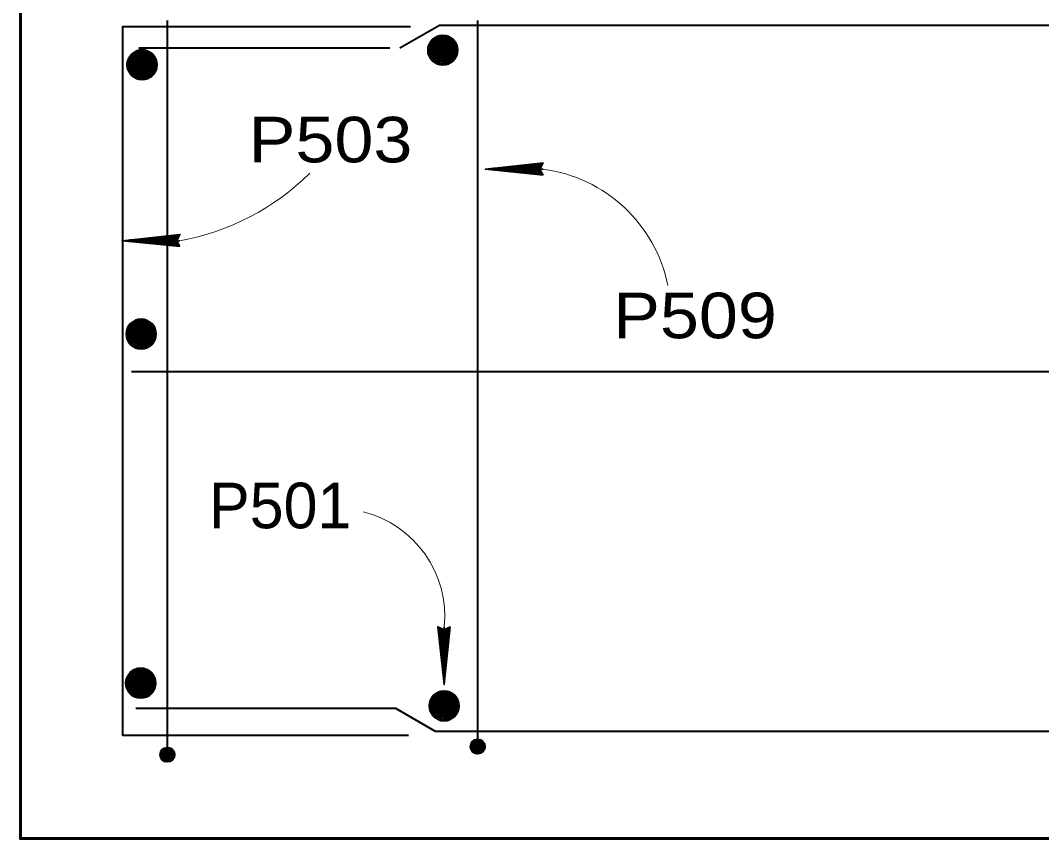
# Model space of a CAD drawing. Extents: x 6.34 to 9.53, y -1.46 to 0.53.
# Drawn here: x 6.7189 to 6.9057, y 0.0454 to 0.195 of the extents above; entities that cross this region are included whole.
import ezdxf

# ---------------------------------------------------------------- set-up
doc = ezdxf.new("R2010")
doc.units = 0
doc.header["$LTSCALE"] = 0.0033
doc.layers.add('1', color=7, linetype='Continuous', lineweight=40)

msp = doc.modelspace()

# ---------------------------------------------------------------- linework, layer by layer
at = {"layer": '1'}
for p, q in [((6.74575, 0.195), (6.74575, 0.062167)), ((6.8025, 0.195), (6.8025, 0.063667)), ((6.794083, 0.191167), (6.798667, 0.189)), ((6.794333, 0.19075), (6.79825, 0.19)), ((6.794333, 0.190583), (6.79825, 0.189833)), ((6.794417, 0.191167), (6.798333, 0.1905)), ((6.794417, 0.191), (6.798333, 0.19025)), ((6.7945, 0.1915), (6.798333, 0.190833)), ((6.796417, 0.190667), (6.79775, 0.191667)), ((6.7985, 0.190833), (6.79725, 0.192)), ((6.7395, 0.188833), (6.743333, 0.188167)), ((6.740583, 0.19), (6.7865, 0.19)), ((6.741417, 0.188), (6.74275, 0.189)), ((6.7435, 0.188167), (6.74225, 0.189333)), ((6.794, 0.188917), (6.797917, 0.188167)), ((6.794, 0.18875), (6.797833, 0.188)), ((6.794083, 0.189333), (6.798, 0.188583)), ((6.794167, 0.18975), (6.798, 0.189)), ((6.794167, 0.189583), (6.798, 0.188833)), ((6.79425, 0.190167), (6.798083, 0.1895)), ((6.79425, 0.19), (6.798083, 0.18925)), ((6.794333, 0.190333), (6.798167, 0.189583)), ((6.739083, 0.1885), (6.743667, 0.186333)), ((6.739167, 0.187083), (6.743, 0.186333)), ((6.739167, 0.186917), (6.743, 0.186167)), ((6.73925, 0.1875), (6.743083, 0.186833)), ((6.73925, 0.187333), (6.743083, 0.186583)), ((6.739333, 0.188083), (6.74325, 0.187333)), ((6.739333, 0.187917), (6.74325, 0.187167)), ((6.739333, 0.187667), (6.743167, 0.186917)), ((6.739417, 0.1885), (6.743333, 0.187833)), ((6.739417, 0.188333), (6.743333, 0.187583)), ((6.793917, 0.188417), (6.79775, 0.187667)), ((6.793917, 0.18825), (6.79775, 0.1875)), ((6.794, 0.1885), (6.797833, 0.187833)), ((6.79825, 0.188), (6.7945, 0.187583)), ((6.738917, 0.18575), (6.74275, 0.185)), ((6.738917, 0.185583), (6.74275, 0.184833)), ((6.739, 0.18625), (6.742917, 0.1855)), ((6.739, 0.186083), (6.742833, 0.185333)), ((6.739, 0.185833), (6.742833, 0.185167)), ((6.739083, 0.186667), (6.743, 0.185917)), ((6.74325, 0.185333), (6.7395, 0.184917)), ((6.743333, 0.138917), (6.742083, 0.140083)), ((6.738917, 0.13925), (6.7435, 0.137083)), ((6.739083, 0.13825), (6.742917, 0.137583)), ((6.739167, 0.138833), (6.743083, 0.138083)), ((6.739167, 0.138667), (6.743083, 0.137917)), ((6.739167, 0.138417), (6.743, 0.137667)), ((6.73925, 0.13925), (6.743167, 0.138583)), ((6.73925, 0.139083), (6.743167, 0.138333)), ((6.739333, 0.139583), (6.743167, 0.138917)), ((6.74125, 0.13875), (6.742583, 0.13975)), ((6.73875, 0.1365), (6.742583, 0.13575)), ((6.738833, 0.137), (6.74275, 0.13625)), ((6.738833, 0.136833), (6.742667, 0.136083)), ((6.738833, 0.136583), (6.742667, 0.135917)), ((6.738917, 0.137417), (6.742833, 0.136667)), ((6.739, 0.137833), (6.742833, 0.137083)), ((6.739, 0.137667), (6.742833, 0.136917)), ((6.739083, 0.138083), (6.742917, 0.137333)), ((6.73875, 0.136333), (6.742583, 0.135583)), ((6.743083, 0.136083), (6.739333, 0.135667)), ((6.738833, 0.075417), (6.743417, 0.07325)), ((6.739083, 0.075), (6.743, 0.07425)), ((6.739083, 0.074833), (6.743, 0.074083)), ((6.739167, 0.075417), (6.743083, 0.07475)), ((6.739167, 0.07525), (6.743083, 0.0745)), ((6.73925, 0.07575), (6.743083, 0.075083)), ((6.741167, 0.074917), (6.7425, 0.075917)), ((6.74325, 0.075083), (6.742, 0.07625)), ((6.73875, 0.073167), (6.742667, 0.072417)), ((6.73875, 0.073), (6.742583, 0.07225)), ((6.738833, 0.073583), (6.74275, 0.072833)), ((6.738917, 0.074), (6.74275, 0.07325)), ((6.738917, 0.073833), (6.74275, 0.073083)), ((6.739, 0.074417), (6.742833, 0.07375)), ((6.739, 0.07425), (6.742833, 0.0735)), ((6.739083, 0.074583), (6.742917, 0.073833)), ((6.738667, 0.072667), (6.7425, 0.071917)), ((6.738667, 0.0725), (6.7425, 0.07175)), ((6.73875, 0.07275), (6.742583, 0.072083)), ((6.743, 0.07225), (6.73925, 0.071833)), ((6.794333, 0.07125), (6.798917, 0.069083)), ((6.794667, 0.07125), (6.798583, 0.070583)), ((6.794667, 0.071083), (6.798583, 0.070333)), ((6.79475, 0.071583), (6.798583, 0.070917)), ((6.796667, 0.07075), (6.798, 0.07175)), ((6.79875, 0.070917), (6.7975, 0.072083)), ((6.794333, 0.069417), (6.79825, 0.068667)), ((6.794417, 0.069833), (6.79825, 0.069083)), ((6.794417, 0.069667), (6.79825, 0.068917)), ((6.7945, 0.07025), (6.798333, 0.069583)), ((6.7945, 0.070083), (6.798333, 0.069333)), ((6.794583, 0.070833), (6.7985, 0.070083)), ((6.794583, 0.070667), (6.7985, 0.069917)), ((6.794583, 0.070417), (6.798417, 0.069667)), ((6.794167, 0.0685), (6.798, 0.06775)), ((6.794167, 0.068333), (6.798, 0.067583)), ((6.79425, 0.069), (6.798167, 0.06825)), ((6.79425, 0.068833), (6.798083, 0.068083)), ((6.79425, 0.068583), (6.798083, 0.067917)), ((6.7985, 0.068083), (6.79475, 0.067667)), ((6.745167, 0.061917), (6.744833, 0.059917)), ((6.74525, 0.061833), (6.744917, 0.059917)), ((6.745333, 0.061833), (6.745, 0.059917)), ((6.745417, 0.061833), (6.745083, 0.059833)), ((6.746583, 0.061667), (6.745083, 0.06175)), ((6.746583, 0.061583), (6.745083, 0.061667)), ((6.745667, 0.061833), (6.74525, 0.059833)), ((6.745833, 0.06175), (6.745417, 0.059833)), ((6.745917, 0.06175), (6.7455, 0.059833)), ((6.746, 0.06175), (6.745583, 0.05975)), ((6.746083, 0.06175), (6.74575, 0.05975)), ((6.746167, 0.061667), (6.745833, 0.05975)), ((6.746333, 0.061667), (6.745917, 0.059667)), ((6.746417, 0.061667), (6.746, 0.059667)), ((6.7465, 0.061667), (6.746167, 0.059667)), ((6.746583, 0.061667), (6.74625, 0.059667)), ((6.801917, 0.063417), (6.801583, 0.061417)), ((6.802, 0.063333), (6.801667, 0.061417)), ((6.802083, 0.063333), (6.80175, 0.061417)), ((6.80325, 0.062), (6.80175, 0.062167)), ((6.80325, 0.061833), (6.80175, 0.062)), ((6.80325, 0.06175), (6.80175, 0.061833)), ((6.80325, 0.06175), (6.80175, 0.061833)), ((6.80325, 0.061667), (6.80175, 0.06175)), ((6.80325, 0.061583), (6.80175, 0.061667)), ((6.802167, 0.063333), (6.801833, 0.061333)), ((6.803333, 0.063167), (6.801833, 0.06325)), ((6.803333, 0.063083), (6.801833, 0.063167)), ((6.803333, 0.063), (6.801833, 0.063083)), ((6.803333, 0.062917), (6.801833, 0.063)), ((6.803333, 0.062833), (6.801833, 0.062917)), ((6.803333, 0.062667), (6.801833, 0.06275)), ((6.803333, 0.062583), (6.801833, 0.062667)), ((6.803333, 0.0625), (6.801833, 0.062583)), ((6.803333, 0.062417), (6.801833, 0.0625)), ((6.803333, 0.062333), (6.801833, 0.062417)), ((6.803333, 0.06225), (6.801833, 0.062333)), ((6.803333, 0.062167), (6.801833, 0.06225)), ((6.802417, 0.063333), (6.802, 0.061333)), ((6.802583, 0.06325), (6.802167, 0.061333)), ((6.802667, 0.06325), (6.80225, 0.061333)), ((6.80275, 0.06325), (6.802333, 0.06125)), ((6.802833, 0.06325), (6.8025, 0.06125)), ((6.802917, 0.063167), (6.802583, 0.06125)), ((6.803083, 0.063167), (6.802667, 0.061167)), ((6.803167, 0.063167), (6.80275, 0.061167)), ((6.80325, 0.063167), (6.802917, 0.061167)), ((6.803333, 0.063167), (6.803, 0.061167)), ((6.8035, 0.063083), (6.803167, 0.061167)), ((6.7465, 0.0605), (6.745, 0.060667)), ((6.7465, 0.060333), (6.745, 0.0605)), ((6.7465, 0.06025), (6.745, 0.060333)), ((6.7465, 0.06025), (6.745, 0.060333)), ((6.7465, 0.060167), (6.745, 0.06025)), ((6.7465, 0.060083), (6.745, 0.060167)), ((6.7465, 0.06), (6.745, 0.060083)), ((6.7465, 0.059917), (6.745, 0.06)), ((6.7465, 0.059833), (6.745, 0.059917)), ((6.7465, 0.05975), (6.745, 0.059833)), ((6.746583, 0.0615), (6.745083, 0.061583)), ((6.746583, 0.061417), (6.745083, 0.0615)), ((6.746583, 0.061333), (6.745083, 0.061417)), ((6.746583, 0.061167), (6.745083, 0.06125)), ((6.746583, 0.061083), (6.745083, 0.061167)), ((6.746583, 0.061), (6.745083, 0.061083)), ((6.746583, 0.060917), (6.745083, 0.061)), ((6.746583, 0.060833), (6.745083, 0.060917)), ((6.746583, 0.06075), (6.745083, 0.060833)), ((6.746583, 0.060667), (6.745083, 0.06075)), ((6.74675, 0.061583), (6.746417, 0.059667)), ((6.80325, 0.0615), (6.80175, 0.061583)), ((6.80325, 0.061417), (6.80175, 0.0615)), ((6.80325, 0.061333), (6.80175, 0.061417)), ((6.80325, 0.06125), (6.80175, 0.061333)), ((6.80325, 0.061083), (6.80175, 0.061167)), ((6.7465, 0.059583), (6.745, 0.059667))]:
    msp.add_line(p, q, dxfattribs=at)
at = {"layer": '1', "lineweight": 60}
for p, q in [((6.794333, 0.191167), (6.794167, 0.18825)), ((6.794583, 0.191167), (6.794333, 0.18825)), ((6.79475, 0.191167), (6.794583, 0.188167)), ((6.794917, 0.191167), (6.794667, 0.188167)), ((6.795083, 0.191167), (6.794917, 0.188167)), ((6.795333, 0.191167), (6.795167, 0.188167)), ((6.795583, 0.191167), (6.795333, 0.188167)), ((6.795667, 0.191083), (6.7955, 0.188167)), ((6.795833, 0.191083), (6.795667, 0.188167)), ((6.796, 0.191083), (6.795833, 0.188167)), ((6.79625, 0.191083), (6.796, 0.188167)), ((6.796417, 0.191083), (6.79625, 0.188167)), ((6.796667, 0.191), (6.796417, 0.188083)), ((6.796917, 0.191), (6.796667, 0.188083)), ((6.797083, 0.191), (6.796917, 0.188083)), ((6.797167, 0.191), (6.797, 0.188083)), ((6.797333, 0.191), (6.797167, 0.188083)), ((6.797417, 0.191), (6.79725, 0.188083)), ((6.797667, 0.190917), (6.797417, 0.188)), ((6.797833, 0.190917), (6.797667, 0.188)), ((6.798, 0.190917), (6.79775, 0.188)), ((6.798167, 0.190917), (6.798, 0.188)), ((6.798417, 0.190917), (6.79825, 0.188)), ((6.798667, 0.189), (6.7985, 0.190833)), ((6.798667, 0.189), (6.793917, 0.18825)), ((6.739333, 0.1885), (6.739167, 0.185583)), ((6.739583, 0.1885), (6.739333, 0.185583)), ((6.73975, 0.1885), (6.739583, 0.1855)), ((6.739917, 0.1885), (6.739667, 0.1855)), ((6.740083, 0.1885), (6.739917, 0.1855)), ((6.740333, 0.1885), (6.740167, 0.1855)), ((6.740583, 0.1885), (6.740333, 0.1855)), ((6.740667, 0.188417), (6.7405, 0.1855)), ((6.740833, 0.188417), (6.740667, 0.1855)), ((6.741, 0.188417), (6.740833, 0.1855)), ((6.74125, 0.188417), (6.741, 0.1855)), ((6.741417, 0.188417), (6.74125, 0.1855)), ((6.741667, 0.188333), (6.741417, 0.185417)), ((6.741917, 0.188333), (6.741667, 0.185417)), ((6.742083, 0.188333), (6.741917, 0.185417)), ((6.742167, 0.188333), (6.742, 0.185417)), ((6.742333, 0.188333), (6.742167, 0.185417)), ((6.742417, 0.188333), (6.74225, 0.185417)), ((6.742667, 0.18825), (6.742417, 0.185333)), ((6.742833, 0.18825), (6.742667, 0.185333)), ((6.743, 0.18825), (6.74275, 0.185333)), ((6.743167, 0.18825), (6.743, 0.185333)), ((6.743417, 0.18825), (6.74325, 0.185333)), ((6.743667, 0.186333), (6.7435, 0.188167)), ((6.743667, 0.186333), (6.738917, 0.185583)), ((6.739167, 0.13925), (6.739, 0.136333)), ((6.739417, 0.13925), (6.739167, 0.136333)), ((6.739583, 0.13925), (6.739417, 0.13625)), ((6.73975, 0.13925), (6.7395, 0.13625)), ((6.739917, 0.13925), (6.73975, 0.13625)), ((6.740167, 0.13925), (6.74, 0.13625)), ((6.740417, 0.13925), (6.740167, 0.13625)), ((6.7405, 0.139167), (6.740333, 0.13625)), ((6.740667, 0.139167), (6.7405, 0.13625)), ((6.740833, 0.139167), (6.740667, 0.13625)), ((6.741083, 0.139167), (6.740833, 0.13625)), ((6.74125, 0.139167), (6.741083, 0.13625)), ((6.7415, 0.139083), (6.74125, 0.136167)), ((6.74175, 0.139083), (6.7415, 0.136167)), ((6.741917, 0.139083), (6.74175, 0.136167)), ((6.742, 0.139083), (6.741833, 0.136167)), ((6.742167, 0.139083), (6.742, 0.136167)), ((6.74225, 0.139083), (6.742083, 0.136167)), ((6.7425, 0.139), (6.74225, 0.136083)), ((6.742667, 0.139), (6.7425, 0.136083)), ((6.742833, 0.139), (6.742583, 0.136083)), ((6.743, 0.139), (6.742833, 0.136083)), ((6.74325, 0.139), (6.743083, 0.136083)), ((6.7435, 0.137083), (6.743333, 0.138917)), ((6.7435, 0.137083), (6.73875, 0.136333)), ((6.739083, 0.075417), (6.738917, 0.0725)), ((6.739333, 0.075417), (6.739083, 0.0725)), ((6.7395, 0.075417), (6.739333, 0.072417)), ((6.739667, 0.075417), (6.739417, 0.072417)), ((6.739833, 0.075417), (6.739667, 0.072417)), ((6.740083, 0.075417), (6.739917, 0.072417)), ((6.740333, 0.075417), (6.740083, 0.072417)), ((6.740417, 0.075333), (6.74025, 0.072417)), ((6.740583, 0.075333), (6.740417, 0.072417)), ((6.74075, 0.075333), (6.740583, 0.072417)), ((6.741, 0.075333), (6.74075, 0.072417)), ((6.741167, 0.075333), (6.741, 0.072417)), ((6.741417, 0.07525), (6.741167, 0.072333)), ((6.741667, 0.07525), (6.741417, 0.072333)), ((6.741833, 0.07525), (6.741667, 0.072333)), ((6.741917, 0.07525), (6.74175, 0.072333)), ((6.742083, 0.07525), (6.741917, 0.072333)), ((6.742167, 0.07525), (6.742, 0.072333)), ((6.742417, 0.075167), (6.742167, 0.07225)), ((6.742583, 0.075167), (6.742417, 0.07225)), ((6.74275, 0.075167), (6.7425, 0.07225)), ((6.742917, 0.075167), (6.74275, 0.07225)), ((6.743167, 0.075167), (6.743, 0.07225)), ((6.743417, 0.07325), (6.74325, 0.075083)), ((6.743417, 0.07325), (6.738667, 0.0725)), ((6.794583, 0.07125), (6.794417, 0.068333)), ((6.794833, 0.07125), (6.794583, 0.068333)), ((6.795, 0.07125), (6.794833, 0.06825)), ((6.795167, 0.07125), (6.794917, 0.06825)), ((6.795333, 0.07125), (6.795167, 0.06825)), ((6.795583, 0.07125), (6.795417, 0.06825)), ((6.795833, 0.07125), (6.795583, 0.06825)), ((6.795917, 0.071167), (6.79575, 0.06825)), ((6.796083, 0.071167), (6.795917, 0.06825)), ((6.79625, 0.071167), (6.796083, 0.06825)), ((6.7965, 0.071167), (6.79625, 0.06825)), ((6.796667, 0.071167), (6.7965, 0.06825)), ((6.796917, 0.071083), (6.796667, 0.068167)), ((6.797167, 0.071083), (6.796917, 0.068167)), ((6.797333, 0.071083), (6.797167, 0.068167)), ((6.797417, 0.071083), (6.79725, 0.068167)), ((6.797583, 0.071083), (6.797417, 0.068167)), ((6.797667, 0.071083), (6.7975, 0.068167)), ((6.797917, 0.071), (6.797667, 0.068083)), ((6.798083, 0.071), (6.797917, 0.068083)), ((6.79825, 0.071), (6.798, 0.068083)), ((6.798417, 0.071), (6.79825, 0.068083)), ((6.798667, 0.071), (6.7985, 0.068083)), ((6.798917, 0.069083), (6.79875, 0.070917)), ((6.798917, 0.069083), (6.794167, 0.068333))]:
    msp.add_line(p, q, dxfattribs=at)
at = {"layer": '1', "lineweight": 35}
for p, q in [((6.81425, 0.168917), (6.806917, 0.168083)), ((6.81425, 0.16875), (6.806917, 0.168)), ((6.81425, 0.168667), (6.806917, 0.167833)), ((6.814333, 0.1685), (6.807, 0.16775)), ((6.8145, 0.167833), (6.803917, 0.167833)), ((6.81425, 0.167), (6.806417, 0.168)), ((6.81425, 0.167), (6.806417, 0.167833)), ((6.81425, 0.166833), (6.806417, 0.16775)), ((6.81425, 0.166833), (6.806417, 0.16775)), ((6.81425, 0.166917), (6.806417, 0.16775)), ((6.747833, 0.155833), (6.7405, 0.155)), ((6.747833, 0.155667), (6.7405, 0.154917)), ((6.747833, 0.155583), (6.7405, 0.15475)), ((6.747917, 0.155417), (6.740583, 0.154667)), ((6.748083, 0.15475), (6.7375, 0.15475)), ((6.747833, 0.153917), (6.74, 0.154917)), ((6.747833, 0.153917), (6.74, 0.15475)), ((6.747833, 0.15375), (6.74, 0.154667)), ((6.747833, 0.15375), (6.74, 0.154667)), ((6.747833, 0.153833), (6.74, 0.154667)), ((6.796417, 0.084167), (6.796417, 0.073583)), ((6.795333, 0.083917), (6.796167, 0.076583)), ((6.7955, 0.083917), (6.79625, 0.076583)), ((6.795583, 0.083917), (6.796417, 0.076583)), ((6.79575, 0.084), (6.7965, 0.076667)), ((6.79725, 0.083917), (6.79625, 0.076083)), ((6.79725, 0.083917), (6.796417, 0.076083)), ((6.797417, 0.083917), (6.7965, 0.076083)), ((6.797417, 0.083917), (6.7965, 0.076083)), ((6.797333, 0.083917), (6.7965, 0.076083))]:
    msp.add_line(p, q, dxfattribs=at)
at = {"layer": '1', "lineweight": 60}
for points in [[(7.30225, 0.212083), (7.30225, 0.045417), (6.718917, 0.045417), (6.718917, 0.212083)], [(6.7935, 0.1895), (6.798667, 0.190167), (6.794083, 0.191167)], [(6.79775, 0.1875), (6.79775, 0.191667), (6.796083, 0.187), (6.796583, 0.192167), (6.7945, 0.187583), (6.79525, 0.192083), (6.796833, 0.187083), (6.793667, 0.190417), (6.7985, 0.190833), (6.79525, 0.187167), (6.79725, 0.192), (6.794083, 0.191167), (6.793917, 0.18825)], [(6.7945, 0.187583), (6.796, 0.189833), (6.793833, 0.19075), (6.795833, 0.192167), (6.796, 0.189917), (6.797667, 0.187583), (6.793667, 0.189917), (6.796417, 0.190667)], [(6.79725, 0.192), (6.796, 0.189833), (6.79825, 0.188)], [(6.74275, 0.184833), (6.74275, 0.189), (6.741083, 0.184333), (6.741583, 0.1895), (6.7395, 0.184917), (6.74025, 0.189417), (6.741833, 0.184417), (6.738667, 0.18775), (6.7435, 0.188167), (6.74025, 0.1845), (6.74225, 0.189333), (6.739083, 0.1885), (6.738917, 0.185583)], [(6.7395, 0.184917), (6.741, 0.187167), (6.738833, 0.188083), (6.740833, 0.1895), (6.741, 0.18725), (6.742667, 0.184917), (6.738667, 0.18725), (6.741417, 0.188)], [(6.74225, 0.189333), (6.741, 0.187167), (6.74325, 0.185333)], [(6.7385, 0.186833), (6.743667, 0.1875), (6.739083, 0.1885)], [(6.742583, 0.135583), (6.742583, 0.13975), (6.740917, 0.135083), (6.741417, 0.14025), (6.739333, 0.135667), (6.740083, 0.140167), (6.741667, 0.135167), (6.7385, 0.1385), (6.743333, 0.138917), (6.740083, 0.13525), (6.742083, 0.140083), (6.738917, 0.13925), (6.73875, 0.136333)], [(6.739333, 0.135667), (6.740833, 0.137917), (6.738667, 0.138833), (6.740667, 0.14025), (6.740833, 0.138), (6.7425, 0.135667), (6.7385, 0.138), (6.74125, 0.13875)], [(6.742083, 0.140083), (6.740833, 0.137917), (6.743083, 0.136083)], [(6.738333, 0.137583), (6.7435, 0.13825), (6.738917, 0.13925)], [(6.73825, 0.07375), (6.743417, 0.074417), (6.738833, 0.075417)], [(6.7425, 0.07175), (6.7425, 0.075917), (6.740833, 0.07125), (6.741333, 0.076417), (6.73925, 0.071833), (6.74, 0.076333), (6.741583, 0.071333), (6.738417, 0.074667), (6.74325, 0.075083), (6.74, 0.071417), (6.742, 0.07625), (6.738833, 0.075417), (6.738667, 0.0725)], [(6.73925, 0.071833), (6.74075, 0.074083), (6.738583, 0.075), (6.740583, 0.076417), (6.74075, 0.074167), (6.742417, 0.071833), (6.738417, 0.074167), (6.741167, 0.074917)], [(6.742, 0.07625), (6.74075, 0.074083), (6.743, 0.07225)], [(6.79375, 0.069583), (6.798917, 0.07025), (6.794333, 0.07125)], [(6.798, 0.067583), (6.798, 0.07175), (6.796333, 0.067083), (6.796833, 0.07225), (6.79475, 0.067667), (6.7955, 0.072167), (6.797083, 0.067167), (6.793917, 0.0705), (6.79875, 0.070917), (6.7955, 0.06725), (6.7975, 0.072083), (6.794333, 0.07125), (6.794167, 0.068333)], [(6.79475, 0.067667), (6.79625, 0.069917), (6.794083, 0.070833), (6.796083, 0.07225), (6.79625, 0.07), (6.797917, 0.067667), (6.793917, 0.07), (6.796667, 0.07075)], [(6.7975, 0.072083), (6.79625, 0.069917), (6.7985, 0.068083)]]:
    msp.add_lwpolyline(points, dxfattribs=at)
at = {"layer": '1'}
for points in [[(6.789917, 0.06425), (6.737667, 0.06425), (6.737667, 0.193917), (6.79025, 0.193917)], [(6.788333, 0.19), (6.795583, 0.194167), (7.16075, 0.194167)], [(6.793917, 0.18825), (6.796, 0.187), (6.79775, 0.1875), (6.798667, 0.189)], [(6.738917, 0.185583), (6.741, 0.184333), (6.74275, 0.184833), (6.743667, 0.186333)], [(6.73875, 0.136333), (6.740833, 0.135083), (6.742583, 0.135583), (6.7435, 0.137083)], [(6.73925, 0.130833), (7.159583, 0.130833), (7.280917, 0.130833)], [(6.738667, 0.0725), (6.74075, 0.07125), (6.7425, 0.07175), (6.743417, 0.07325)], [(6.74, 0.06925), (6.7875, 0.06925), (6.79475, 0.065083), (7.168917, 0.065083)], [(6.794167, 0.068333), (6.79625, 0.067083), (6.798, 0.067583), (6.798917, 0.069083)], [(6.8025, 0.063583), (6.802833, 0.061), (6.803333, 0.063333), (6.80225, 0.061), (6.801833, 0.063417), (6.8015, 0.061417), (6.803583, 0.061417), (6.80125, 0.062333), (6.803833, 0.062083), (6.8015, 0.063083), (6.803833, 0.06275), (6.80125, 0.061917), (6.803, 0.0635), (6.803167, 0.061083), (6.801333, 0.06275), (6.80375, 0.061667), (6.803333, 0.063333), (6.801833, 0.063417), (6.80125, 0.062333), (6.8015, 0.061417), (6.80225, 0.061), (6.803167, 0.061083), (6.80375, 0.061667), (6.802667, 0.062333), (6.80175, 0.061167), (6.8015, 0.063083), (6.802667, 0.062333), (6.803167, 0.063417), (6.803833, 0.062417), (6.80275, 0.062333), (6.8015, 0.0615), (6.80275, 0.0635), (6.803083, 0.062167), (6.803583, 0.061417)], [(6.74575, 0.062083), (6.746083, 0.0595), (6.746583, 0.061833), (6.7455, 0.0595), (6.745083, 0.061917), (6.74475, 0.059917), (6.746833, 0.059917), (6.7445, 0.060833), (6.747083, 0.060583), (6.74475, 0.061583), (6.747083, 0.06125), (6.7445, 0.060417), (6.74625, 0.062), (6.746417, 0.059583), (6.744583, 0.06125), (6.747, 0.060167), (6.746583, 0.061833), (6.745083, 0.061917), (6.7445, 0.060833), (6.74475, 0.059917), (6.7455, 0.0595), (6.746417, 0.059583), (6.747, 0.060167), (6.745917, 0.060833), (6.745, 0.059667), (6.74475, 0.061583), (6.745917, 0.060833), (6.746417, 0.061917), (6.747083, 0.060917), (6.746, 0.060833), (6.74475, 0.06), (6.746, 0.062), (6.746333, 0.060667), (6.746833, 0.059917)]]:
    msp.add_lwpolyline(points, dxfattribs=at)
at = {"layer": '1', "lineweight": 35}
for points in [[(6.8145, 0.16675), (6.803917, 0.167833), (6.8145, 0.169), (6.813917, 0.167833)], [(6.81375, 0.16775), (6.809083, 0.167667), (6.809083, 0.16775), (6.81, 0.16775), (6.81375, 0.167667), (6.81075, 0.167583), (6.813917, 0.1675), (6.811667, 0.167417), (6.813917, 0.167333), (6.810417, 0.167583), (6.80575, 0.16775), (6.806667, 0.168), (6.805417, 0.168), (6.81375, 0.168), (6.811333, 0.168167), (6.813917, 0.168167), (6.808583, 0.16775), (6.813917, 0.168417)], [(6.748083, 0.153667), (6.7375, 0.15475), (6.748083, 0.155917), (6.7475, 0.15475)], [(6.747333, 0.154667), (6.742667, 0.154583), (6.742667, 0.154667), (6.743583, 0.154667), (6.747333, 0.154583), (6.744333, 0.1545), (6.7475, 0.154417), (6.74525, 0.154333), (6.7475, 0.15425), (6.744, 0.1545), (6.739333, 0.154667), (6.74025, 0.154917), (6.739, 0.154917), (6.747333, 0.154917), (6.744917, 0.155083), (6.7475, 0.155083), (6.742167, 0.154667), (6.7475, 0.155333)], [(6.7975, 0.084167), (6.796417, 0.073583), (6.79525, 0.084167), (6.796417, 0.083583)], [(6.7965, 0.083417), (6.796583, 0.07875), (6.7965, 0.07875), (6.7965, 0.079667), (6.796583, 0.083417), (6.796667, 0.080417), (6.79675, 0.083583), (6.796833, 0.081333), (6.796917, 0.083583), (6.796667, 0.080083), (6.7965, 0.075417), (6.79625, 0.076333), (6.79625, 0.075083), (6.79625, 0.083417), (6.796083, 0.081), (6.796083, 0.083583), (6.7965, 0.07825), (6.795833, 0.083583)]]:
    msp.add_lwpolyline(points, close=True, dxfattribs=at)
for points in [[(6.81375, 0.16775), (6.814167, 0.167), (6.813917, 0.16725), (6.81375, 0.167583), (6.8135, 0.1675), (6.813667, 0.167167), (6.813833, 0.167917), (6.814, 0.168417), (6.81425, 0.168833)], [(6.747333, 0.154667), (6.74775, 0.153917), (6.7475, 0.154167), (6.747333, 0.1545), (6.747083, 0.154417), (6.74725, 0.154083), (6.747417, 0.154833), (6.747583, 0.155333), (6.747833, 0.15575)], [(6.7965, 0.083417), (6.79725, 0.083833), (6.797, 0.083583), (6.796667, 0.083417), (6.79675, 0.083167), (6.797083, 0.083333), (6.796333, 0.0835), (6.795833, 0.083667), (6.795417, 0.083917)]]:
    msp.add_lwpolyline(points, dxfattribs=at)
at = {"layer": '1', "lineweight": 60}
for centre in [(6.796167, 0.1896), (6.741167, 0.186933), (6.741, 0.137683), (6.740917, 0.07385), (6.796417, 0.069683)]:
    msp.add_circle(centre, 0.00264, dxfattribs=at)
at = {"layer": '1'}
for centre in [(6.80255, 0.06225), (6.7458, 0.06075)]:
    msp.add_circle(centre, 0.00132, dxfattribs=at)
at = {"layer": '1', "lineweight": 13}
for centre, radius, start, end in [((6.739955, 0.199437), 0.04542, 280.3093, 314.57625), ((6.81104, 0.141223), 0.026834, 11.52271, 82.59129), ((6.776921, 0.086135), 0.019595, 354.23615, 76.23474)]:
    msp.add_arc(centre, radius, start, end, dxfattribs=at)

# ---------------------------------------------------------------- texts
at = {"layer": '1', "width": 1.15}
for s, p in [('P503', (6.760667, 0.169083)), ('P509', (6.827333, 0.136917))]:
    msp.add_text(s, height=0.008334, dxfattribs=at).set_placement(p)
at = {"layer": '1'}
msp.add_text('P501', height=0.008334, dxfattribs=at).set_placement((6.753417, 0.102167))

doc.saveas('drawing.dxf')
